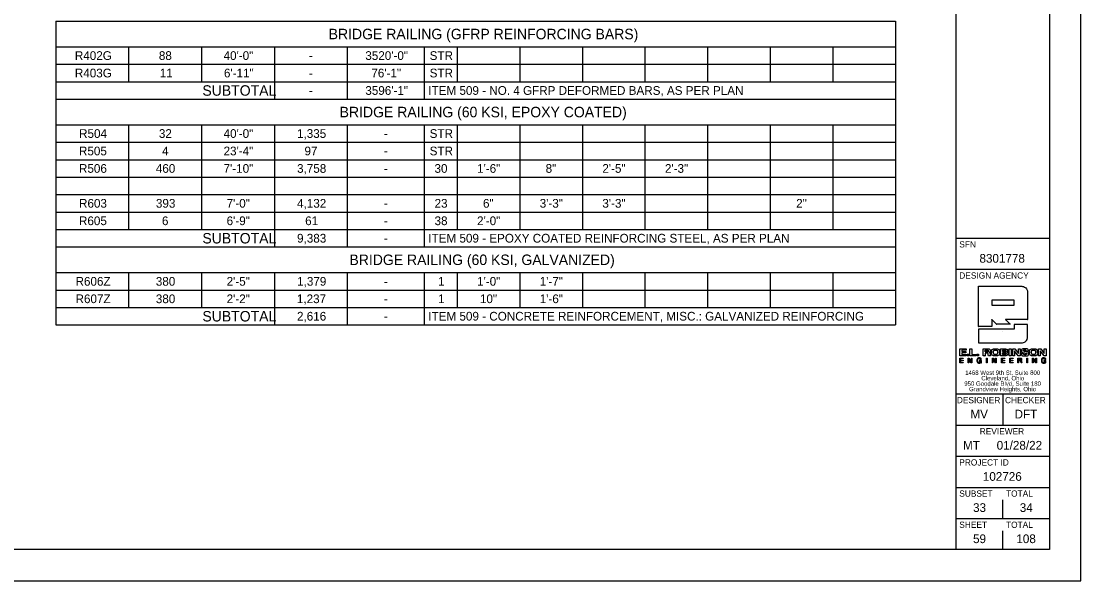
# Model space of a CAD drawing. Extents: x 0 to 34, y 0 to 22.
# Drawn here: x 17 to 34, y 0 to 8.98 of the extents above; entities that cross this region are included whole.
import ezdxf

# ---------------------------------------------------------------- set-up
doc = ezdxf.new("R2010")
doc.units = 0
for name, color, linetype in [('Default', 7, 'Continuous'), ('SH_Border', 7, 'Continuous'), ('SH_Cut_Line', 7, 'Continuous'), ('SH_Data', 7, 'Continuous')]:
    doc.layers.add(name, color=color, linetype=linetype)

msp = doc.modelspace()

# ---------------------------------------------------------------- linework, layer by layer
at = {"layer": 'Default'}
for p, q in [((17.554, 8.981), (31.027, 8.981)), ((17.554, 8.981), (17.554, 4.106)), ((31.027, 8.981), (31.027, 4.106)), ((17.554, 8.569), (31.027, 8.569)), ((18.723, 8.569), (18.723, 8.009)), ((19.892, 8.569), (19.892, 8.009)), ((21.062, 8.569), (21.062, 7.729)), ((22.231, 8.569), (22.231, 7.729)), ((23.467, 8.569), (23.467, 7.729)), ((23.994, 8.569), (23.994, 8.009)), ((24.998, 8.569), (24.998, 8.009)), ((26.003, 8.569), (26.003, 8.009)), ((27.008, 8.569), (27.008, 8.009)), ((28.013, 8.569), (28.013, 8.009)), ((29.017, 8.569), (29.017, 8.009)), ((30.022, 8.569), (30.022, 8.009)), ((17.554, 8.289), (31.027, 8.289)), ((17.554, 8.009), (31.027, 8.009)), ((17.554, 7.729), (31.027, 7.729)), ((17.554, 7.318), (31.027, 7.318)), ((18.723, 7.318), (18.723, 5.638)), ((19.892, 7.318), (19.892, 5.638)), ((21.062, 7.318), (21.062, 5.358)), ((22.231, 7.318), (22.231, 5.358)), ((23.467, 7.318), (23.467, 5.358)), ((23.994, 7.318), (23.994, 5.638)), ((24.998, 7.318), (24.998, 5.638)), ((26.003, 7.318), (26.003, 5.638)), ((27.008, 7.318), (27.008, 5.638)), ((28.013, 7.318), (28.013, 5.638)), ((29.017, 7.318), (29.017, 5.638)), ((30.022, 7.318), (30.022, 5.638)), ((17.554, 7.038), (31.027, 7.038)), ((17.554, 6.758), (31.027, 6.758)), ((17.554, 6.478), (31.027, 6.478)), ((17.554, 6.198), (31.027, 6.198)), ((17.554, 5.918), (31.027, 5.918)), ((17.554, 5.638), (31.027, 5.638)), ((17.554, 5.358), (31.027, 5.358)), ((17.554, 4.946), (31.027, 4.946)), ((18.723, 4.946), (18.723, 4.386)), ((19.892, 4.946), (19.892, 4.386)), ((21.062, 4.946), (21.062, 4.106)), ((22.231, 4.946), (22.231, 4.106)), ((23.467, 4.946), (23.467, 4.106)), ((23.994, 4.946), (23.994, 4.386)), ((24.998, 4.946), (24.998, 4.386)), ((26.003, 4.946), (26.003, 4.386)), ((27.008, 4.946), (27.008, 4.386)), ((28.013, 4.946), (28.013, 4.386)), ((29.017, 4.946), (29.017, 4.386)), ((30.022, 4.946), (30.022, 4.386)), ((17.554, 4.666), (31.027, 4.666)), ((17.554, 4.386), (31.027, 4.386)), ((17.554, 4.106), (31.027, 4.106))]:
    msp.add_line(p, q, dxfattribs=at)
at = {"layer": 'SH_Border'}
for p, q in [((32, 0.5), (32, 21.5)), ((32, 5.5), (33.5, 5.5)), ((32, 5), (33.5, 5)), ((32, 3), (33.5, 3)), ((32.75, 3), (32.75, 2.5)), ((32, 2.5), (33.5, 2.5)), ((32, 2), (33.5, 2)), ((32, 1.5), (33.5, 1.5)), ((32, 1), (33.5, 1))]:
    msp.add_line(p, q, dxfattribs=at)
msp.add_lwpolyline([(1.5, 21.5), (33.5, 21.5), (33.5, 0.5), (1.5, 0.5)], close=True, dxfattribs=at)
at = {"layer": 'SH_Cut_Line'}
msp.add_lwpolyline([(0, 0), (34, 0), (34, 22), (0, 22)], close=True, dxfattribs=at)
at = {"layer": 'SH_Data'}
for p, q in [((32.929, 4.503), (32.574, 4.503)), ((32.574, 4.503), (32.574, 4.425)), ((32.574, 4.425), (32.929, 4.425)), ((32.929, 4.425), (32.929, 4.503)), ((32.75, 4), (32.75, 4)), ((32.463, 3.701), (32.463, 3.673)), ((32.743, 3.702), (32.743, 3.678)), ((32.743, 3.659), (32.743, 3.633)), ((33.001, 3.566), (33.001, 3.539)), ((33.001, 3.539), (33.023, 3.539)), ((32.75, 1), (32.75, 1.3)), ((32.75, 0.5), (32.75, 0.8)), ((32.375, 0.675), (32.375, 0.675))]:
    msp.add_line(p, q, dxfattribs=at)
for points in [[(32.059, 3.575), (32.114, 3.575), (32.114, 3.566), (32.07, 3.566), (32.07, 3.541), (32.111, 3.541), (32.111, 3.532), (32.07, 3.532), (32.07, 3.505), (32.114, 3.505), (32.114, 3.496), (32.059, 3.496), (32.059, 3.575)], [(32.06, 3.721), (32.161, 3.721), (32.161, 3.701), (32.089, 3.701), (32.089, 3.678), (32.158, 3.678), (32.158, 3.658), (32.089, 3.658), (32.089, 3.633), (32.162, 3.633), (32.162, 3.613), (32.06, 3.613), (32.06, 3.721)], [(32.175, 3.639), (32.205, 3.639), (32.205, 3.613), (32.175, 3.613), (32.175, 3.639)], [(32.191, 3.575), (32.203, 3.575), (32.244, 3.511), (32.244, 3.511), (32.244, 3.575), (32.254, 3.575), (32.254, 3.496), (32.243, 3.496), (32.202, 3.559), (32.201, 3.559), (32.201, 3.496), (32.191, 3.496), (32.191, 3.575)], [(32.22, 3.721), (32.249, 3.721), (32.249, 3.634), (32.316, 3.634), (32.316, 3.613), (32.22, 3.613), (32.22, 3.721)], [(32.331, 3.639), (32.361, 3.639), (32.361, 3.613), (32.331, 3.613), (32.331, 3.639)], [(32.487, 3.575), (32.498, 3.575), (32.498, 3.496), (32.487, 3.496), (32.487, 3.575)], [(32.581, 3.575), (32.592, 3.575), (32.633, 3.511), (32.633, 3.511), (32.633, 3.575), (32.643, 3.575), (32.643, 3.496), (32.632, 3.496), (32.591, 3.559), (32.591, 3.559), (32.591, 3.496), (32.581, 3.496), (32.581, 3.575)], [(32.726, 3.575), (32.781, 3.575), (32.781, 3.566), (32.737, 3.566), (32.737, 3.541), (32.778, 3.541), (32.778, 3.532), (32.737, 3.532), (32.737, 3.505), (32.781, 3.505), (32.781, 3.496), (32.726, 3.496), (32.726, 3.575)], [(32.851, 3.721), (32.881, 3.721), (32.881, 3.613), (32.851, 3.613), (32.851, 3.721)], [(32.859, 3.575), (32.913, 3.575), (32.913, 3.566), (32.869, 3.566), (32.869, 3.541), (32.91, 3.541), (32.91, 3.532), (32.869, 3.532), (32.869, 3.505), (32.913, 3.505), (32.913, 3.496), (32.859, 3.496), (32.859, 3.575)], [(32.999, 3.721), (33.027, 3.721), (33.027, 3.613), (32.995, 3.613), (32.936, 3.689), (32.936, 3.689), (32.936, 3.613), (32.907, 3.613), (32.907, 3.721), (32.941, 3.721), (32.999, 3.646), (32.999, 3.646), (32.999, 3.721)], [(33.133, 3.575), (33.143, 3.575), (33.143, 3.496), (33.133, 3.496), (33.133, 3.575)], [(33.226, 3.575), (33.237, 3.575), (33.279, 3.511), (33.279, 3.511), (33.279, 3.575), (33.289, 3.575), (33.289, 3.496), (33.277, 3.496), (33.236, 3.559), (33.236, 3.559), (33.236, 3.496), (33.226, 3.496), (33.226, 3.575)], [(33.413, 3.721), (33.442, 3.721), (33.442, 3.613), (33.41, 3.613), (33.35, 3.689), (33.35, 3.689), (33.35, 3.613), (33.321, 3.613), (33.321, 3.721), (33.356, 3.721), (33.413, 3.646), (33.413, 3.646), (33.413, 3.721)]]:
    msp.add_lwpolyline(points, dxfattribs=at)
for points, degree in [([(32.356, 4.083), (32.356, 4.086), (32.356, 4.724), (32.356, 4.727)], 2), ([(32.356, 4.727), (32.36, 4.727), (33.03, 4.727), (33.034, 4.727), (33.096, 4.727), (33.147, 4.677), (33.147, 4.614)], 3), ([(33.147, 4.614), (33.147, 4.612), (33.147, 4.194), (33.147, 4.192)], 2), ([(32.929, 4.115), (32.929, 4.115), (33.147, 4.115), (33.147, 4.115), (33.147, 4.115), (33.147, 3.933), (33.147, 3.933), (33.147, 3.87), (33.096, 3.82), (33.034, 3.82), (33.034, 3.82), (32.356, 3.82), (32.356, 3.82), (32.356, 3.82), (32.356, 4.037), (32.356, 4.037), (32.356, 4.037), (32.929, 4.037), (32.929, 4.037), (32.929, 4.037), (32.929, 4.115), (32.929, 4.115)], 3), ([(32.574, 4.083), (32.573, 4.083), (32.357, 4.083), (32.356, 4.083)], 2), ([(32.645, 4.121), (32.645, 4.121), (32.574, 4.191), (32.574, 4.192)], 2), ([(32.574, 4.192), (32.574, 4.191), (32.574, 4.083), (32.574, 4.083)], 2), ([(32.866, 4.121), (32.865, 4.121), (32.646, 4.121), (32.645, 4.121)], 2), ([(33.147, 4.192), (33.145, 4.192), (32.795, 4.192), (32.793, 4.192)], 2), ([(32.793, 4.192), (32.793, 4.191), (32.866, 4.121), (32.866, 4.121)], 2), ([(32.396, 3.506), (32.39, 3.498), (32.38, 3.494), (32.37, 3.494), (32.347, 3.494), (32.333, 3.514), (32.333, 3.534), (32.333, 3.557), (32.346, 3.577), (32.37, 3.577), (32.388, 3.577), (32.401, 3.569), (32.404, 3.551), (32.404, 3.551), (32.394, 3.551), (32.394, 3.551), (32.392, 3.562), (32.382, 3.568), (32.37, 3.568), (32.351, 3.568), (32.344, 3.551), (32.344, 3.534), (32.344, 3.518), (32.353, 3.503), (32.37, 3.503), (32.387, 3.503), (32.396, 3.515), (32.396, 3.529), (32.396, 3.529), (32.371, 3.529), (32.371, 3.529), (32.371, 3.529), (32.371, 3.538), (32.371, 3.538), (32.371, 3.538), (32.405, 3.538), (32.405, 3.538), (32.405, 3.538), (32.405, 3.496), (32.405, 3.496), (32.405, 3.496), (32.398, 3.496), (32.398, 3.496), (32.398, 3.496), (32.396, 3.506), (32.396, 3.506)], 3), ([(32.433, 3.613), (32.433, 3.613), (32.433, 3.721), (32.433, 3.721)], 2), ([(32.433, 3.721), (32.433, 3.721), (32.512, 3.721), (32.512, 3.721), (32.542, 3.721), (32.545, 3.703), (32.546, 3.692)], 3), ([(32.463, 3.613), (32.462, 3.613), (32.433, 3.613), (32.433, 3.613)], 2), ([(32.499, 3.653), (32.499, 3.653), (32.463, 3.653), (32.463, 3.653)], 2), ([(32.463, 3.673), (32.463, 3.673), (32.502, 3.673), (32.502, 3.673), (32.508, 3.673), (32.516, 3.677), (32.516, 3.687), (32.516, 3.698), (32.507, 3.701), (32.5, 3.701), (32.5, 3.701), (32.463, 3.701), (32.463, 3.701), (32.463, 3.701), (32.463, 3.673), (32.463, 3.673)], 3), ([(32.463, 3.673), (32.476, 3.673), (32.489, 3.673), (32.508, 3.673), (32.516, 3.677), (32.516, 3.698), (32.507, 3.701), (32.488, 3.701), (32.475, 3.701), (32.463, 3.701)], 3), ([(32.463, 3.653), (32.463, 3.652), (32.463, 3.613), (32.463, 3.613)], 2), ([(32.518, 3.613), (32.516, 3.618), (32.516, 3.622), (32.516, 3.634), (32.515, 3.649), (32.508, 3.65), (32.499, 3.653)], 3), ([(32.55, 3.613), (32.55, 3.613), (32.518, 3.613), (32.518, 3.613)], 2), ([(32.546, 3.692), (32.544, 3.679), (32.542, 3.67), (32.53, 3.666)], 2), ([(32.53, 3.666), (32.53, 3.666), (32.53, 3.665), (32.53, 3.665)], 2), ([(32.53, 3.665), (32.543, 3.663), (32.544, 3.647), (32.544, 3.636)], 2), ([(32.544, 3.636), (32.544, 3.631), (32.548, 3.619), (32.55, 3.613)], 2), ([(32.631, 3.61), (32.573, 3.61), (32.567, 3.645), (32.565, 3.667), (32.564, 3.69), (32.573, 3.724), (32.631, 3.724)], 3), ([(32.631, 3.63), (32.658, 3.63), (32.667, 3.65), (32.667, 3.667), (32.667, 3.684), (32.658, 3.704), (32.631, 3.704), (32.604, 3.704), (32.595, 3.684), (32.595, 3.667), (32.595, 3.65), (32.604, 3.63), (32.631, 3.63)], 3), ([(32.631, 3.704), (32.604, 3.704), (32.595, 3.684), (32.595, 3.667), (32.595, 3.65), (32.604, 3.63), (32.631, 3.63)], 3), ([(32.631, 3.724), (32.69, 3.724), (32.695, 3.689), (32.697, 3.667), (32.699, 3.644), (32.69, 3.61), (32.631, 3.61)], 3), ([(32.631, 3.63), (32.658, 3.63), (32.667, 3.65), (32.667, 3.667), (32.667, 3.684), (32.658, 3.704), (32.631, 3.704)], 3), ([(32.714, 3.613), (32.714, 3.613), (32.714, 3.721), (32.714, 3.721)], 2), ([(32.714, 3.721), (32.714, 3.721), (32.795, 3.721), (32.795, 3.721)], 2), ([(32.829, 3.645), (32.827, 3.632), (32.824, 3.613), (32.791, 3.613), (32.791, 3.613), (32.714, 3.613), (32.714, 3.613)], 3), ([(32.743, 3.678), (32.743, 3.678), (32.784, 3.678), (32.784, 3.678), (32.791, 3.678), (32.796, 3.682), (32.796, 3.69), (32.796, 3.697), (32.793, 3.702), (32.78, 3.702), (32.78, 3.702), (32.743, 3.702), (32.743, 3.702), (32.743, 3.702), (32.743, 3.678), (32.743, 3.678)], 3), ([(32.743, 3.678), (32.757, 3.678), (32.771, 3.678), (32.791, 3.681), (32.791, 3.683), (32.792, 3.697), (32.793, 3.702), (32.768, 3.702), (32.756, 3.702), (32.743, 3.702)], 3), ([(32.743, 3.633), (32.743, 3.633), (32.787, 3.633), (32.787, 3.633), (32.796, 3.633), (32.8, 3.639), (32.8, 3.646), (32.8, 3.655), (32.794, 3.659), (32.784, 3.659), (32.784, 3.659), (32.743, 3.659), (32.743, 3.659), (32.743, 3.659), (32.743, 3.633), (32.743, 3.633)], 3), ([(32.743, 3.633), (32.758, 3.633), (32.772, 3.633), (32.796, 3.633), (32.8, 3.639), (32.8, 3.655), (32.794, 3.659), (32.77, 3.659), (32.757, 3.659), (32.743, 3.659)], 3), ([(32.795, 3.721), (32.81, 3.718), (32.826, 3.714), (32.826, 3.694)], 2), ([(32.826, 3.694), (32.824, 3.686), (32.822, 3.675), (32.812, 3.672)], 2), ([(32.812, 3.672), (32.812, 3.672), (32.812, 3.672), (32.812, 3.672)], 2), ([(32.812, 3.672), (32.824, 3.67), (32.827, 3.656), (32.829, 3.645)], 2), ([(32.991, 3.575), (32.991, 3.575), (33.027, 3.575), (33.028, 3.575), (33.042, 3.575), (33.051, 3.567), (33.051, 3.554)], 3), ([(32.991, 3.496), (32.991, 3.497), (32.991, 3.574), (32.991, 3.575)], 2), ([(33.126, 3.69), (33.124, 3.704), (33.111, 3.706), (33.099, 3.706), (33.087, 3.706), (33.079, 3.7), (33.079, 3.693), (33.079, 3.687), (33.084, 3.684), (33.091, 3.683), (33.091, 3.683), (33.128, 3.677), (33.128, 3.677), (33.148, 3.673), (33.163, 3.666), (33.163, 3.646), (33.163, 3.626), (33.149, 3.61), (33.107, 3.61), (33.08, 3.61), (33.046, 3.613), (33.045, 3.647), (33.045, 3.647), (33.079, 3.647), (33.079, 3.647), (33.079, 3.632), (33.094, 3.629), (33.107, 3.629), (33.121, 3.629), (33.13, 3.634), (33.13, 3.643), (33.13, 3.651), (33.123, 3.654), (33.112, 3.655), (33.112, 3.655), (33.085, 3.66), (33.085, 3.66), (33.066, 3.662), (33.047, 3.668), (33.047, 3.69), (33.047, 3.715), (33.067, 3.724), (33.101, 3.724), (33.124, 3.724), (33.157, 3.721), (33.159, 3.69), (33.159, 3.69), (33.126, 3.69), (33.126, 3.69)], 3), ([(33.242, 3.61), (33.183, 3.61), (33.178, 3.645), (33.176, 3.667), (33.174, 3.69), (33.183, 3.724), (33.242, 3.724)], 3), ([(33.242, 3.63), (33.269, 3.63), (33.278, 3.65), (33.278, 3.667), (33.278, 3.684), (33.269, 3.704), (33.242, 3.704), (33.215, 3.704), (33.205, 3.684), (33.205, 3.667), (33.205, 3.65), (33.215, 3.63), (33.242, 3.63)], 3), ([(33.242, 3.704), (33.215, 3.704), (33.205, 3.684), (33.205, 3.667), (33.205, 3.65), (33.215, 3.63), (33.242, 3.63)], 3), ([(33.242, 3.724), (33.3, 3.724), (33.306, 3.689), (33.308, 3.667), (33.309, 3.644), (33.3, 3.61), (33.242, 3.61)], 3), ([(33.242, 3.63), (33.269, 3.63), (33.278, 3.65), (33.278, 3.667), (33.278, 3.684), (33.269, 3.704), (33.242, 3.704)], 3), ([(33.43, 3.506), (33.424, 3.498), (33.414, 3.494), (33.405, 3.494), (33.382, 3.494), (33.368, 3.514), (33.368, 3.534), (33.368, 3.557), (33.38, 3.577), (33.405, 3.577), (33.422, 3.577), (33.436, 3.569), (33.439, 3.551), (33.439, 3.551), (33.429, 3.551), (33.429, 3.551), (33.426, 3.562), (33.417, 3.568), (33.405, 3.568), (33.386, 3.568), (33.378, 3.551), (33.378, 3.534), (33.378, 3.518), (33.388, 3.503), (33.405, 3.503), (33.421, 3.503), (33.431, 3.515), (33.43, 3.529), (33.43, 3.529), (33.405, 3.529), (33.405, 3.529), (33.405, 3.529), (33.405, 3.538), (33.405, 3.538), (33.405, 3.538), (33.44, 3.538), (33.44, 3.538), (33.44, 3.538), (33.44, 3.496), (33.44, 3.496), (33.44, 3.496), (33.433, 3.496), (33.433, 3.496), (33.433, 3.496), (33.43, 3.506), (33.43, 3.506)], 3), ([(33.001, 3.496), (33.001, 3.496), (32.991, 3.496), (32.991, 3.496)], 2), ([(33.023, 3.539), (33.033, 3.539), (33.041, 3.541), (33.041, 3.552), (33.041, 3.56), (33.037, 3.566), (33.027, 3.566), (33.027, 3.566), (33.001, 3.566), (33.001, 3.566), (33.001, 3.566), (33.001, 3.539), (33.001, 3.539), (33.001, 3.539), (33.023, 3.539), (33.023, 3.539)], 3), ([(33.023, 3.539), (33.033, 3.539), (33.041, 3.541), (33.041, 3.56), (33.037, 3.566), (33.018, 3.566), (33.01, 3.566), (33.001, 3.566)], 3), ([(33.04, 3.516), (33.038, 3.523), (33.037, 3.53), (33.027, 3.53), (33.027, 3.53), (33.001, 3.53), (33.001, 3.53)], 3), ([(33.001, 3.53), (33.001, 3.53), (33.001, 3.496), (33.001, 3.496)], 2), ([(33.051, 3.554), (33.049, 3.545), (33.047, 3.537), (33.038, 3.534)], 2), ([(33.038, 3.534), (33.038, 3.534), (33.038, 3.534), (33.038, 3.534)], 2), ([(33.038, 3.534), (33.044, 3.529), (33.047, 3.525), (33.048, 3.518)], 2), ([(33.043, 3.496), (33.042, 3.5), (33.041, 3.508), (33.04, 3.516)], 2), ([(33.054, 3.496), (33.054, 3.496), (33.043, 3.496), (33.043, 3.496)], 2), ([(33.048, 3.518), (33.049, 3.51), (33.052, 3.502), (33.054, 3.496)], 2)]:
    msp.add_open_spline(points, degree=degree, dxfattribs=at)

# ---------------------------------------------------------------- texts
at = {"layer": 'Default'}
for s, height, p in [('BRIDGE RAILING (GFRP REINFORCING BARS)', 0.168, (21.933, 8.691)), ('R402G', 0.14, (17.861, 8.359)), ('88', 0.14, (19.209, 8.359)), ('40\'-0"', 0.14, (20.247, 8.359)), ('3520\'-0"', 0.14, (22.521, 8.359)), ('STR', 0.14, (23.553, 8.359)), ('-', 0.14, (21.617, 8.359)), ('R403G', 0.14, (17.861, 8.079)), ('11', 0.14, (19.223, 8.079)), ('6\'-11"', 0.14, (20.253, 8.079)), ('76\'-1"', 0.14, (22.618, 8.079)), ('STR', 0.14, (23.553, 8.079)), ('-', 0.14, (21.617, 8.079)), ('SUBTOTAL', 0.168, (19.907, 7.785)), ('-', 0.154, (21.614, 7.795)), ('3596\'-1"', 0.14, (22.521, 7.799)), ('ITEM 509 - NO. 4 GFRP DEFORMED BARS, AS PER PLAN', 0.14, (23.532, 7.799)), ('BRIDGE RAILING (60 KSI, EPOXY COATED)', 0.168, (22.109, 7.439)), ('R504', 0.14, (17.929, 7.108)), ('32', 0.14, (19.209, 7.108)), ('40\'-0"', 0.14, (20.247, 7.108)), ('1,335', 0.14, (21.425, 7.108)), ('-', 0.14, (22.82, 7.108)), ('STR', 0.14, (23.553, 7.108)), ('R505', 0.14, (17.927, 6.828)), ('4', 0.14, (19.26, 6.828)), ('23\'-4"', 0.14, (20.247, 6.828)), ('97', 0.14, (21.545, 6.828)), ('-', 0.14, (22.82, 6.828)), ('STR', 0.14, (23.553, 6.828)), ('R506', 0.14, (17.927, 6.548)), ('460', 0.14, (19.16, 6.548)), ('7\'-10"', 0.14, (20.247, 6.548)), ('3,758', 0.14, (21.426, 6.548)), ('30', 0.14, (23.631, 6.548)), ('1\'-6"', 0.14, (24.314, 6.548)), ('8"', 0.14, (25.414, 6.548)), ('2\'-5"', 0.14, (26.324, 6.548)), ('2\'-3"', 0.14, (27.328, 6.548)), ('-', 0.14, (22.82, 6.548)), ('R603', 0.14, (17.928, 5.988)), ('393', 0.14, (19.161, 5.988)), ('7\'-0"', 0.14, (20.296, 5.988)), ('4,132', 0.14, (21.426, 5.988)), ('23', 0.14, (23.632, 5.988)), ('6"', 0.14, (24.409, 5.988)), ('3\'-3"', 0.14, (25.319, 5.988)), ('3\'-3"', 0.14, (26.324, 5.988)), ('2"', 0.14, (29.433, 5.988)), ('-', 0.14, (22.82, 5.988)), ('R605', 0.14, (17.927, 5.708)), ('6', 0.14, (19.258, 5.708)), ('6\'-9"', 0.14, (20.296, 5.708)), ('61', 0.14, (21.556, 5.708)), ('38', 0.14, (23.632, 5.708)), ('2\'-0"', 0.14, (24.314, 5.708)), ('-', 0.14, (22.82, 5.708)), ('SUBTOTAL', 0.168, (19.907, 5.414)), ('9,383', 0.14, (21.426, 5.428)), ('-', 0.14, (22.82, 5.428)), ('ITEM 509 - EPOXY COATED REINFORCING STEEL, AS PER PLAN', 0.14, (23.532, 5.428)), ('BRIDGE RAILING (60 KSI, GALVANIZED)', 0.168, (22.266, 5.068)), ('R606Z', 0.14, (17.872, 4.736)), ('380', 0.14, (19.16, 4.736)), ('2\'-5"', 0.14, (20.296, 4.736)), ('1,379', 0.14, (21.427, 4.736)), ('-', 0.14, (22.82, 4.736)), ('1', 0.14, (23.688, 4.736)), ('1\'-0"', 0.14, (24.314, 4.736)), ('1\'-7"', 0.14, (25.319, 4.736)), ('R607Z', 0.14, (17.872, 4.456)), ('380', 0.14, (19.16, 4.456)), ('2\'-2"', 0.14, (20.296, 4.456)), ('1,237', 0.14, (21.423, 4.456)), ('1', 0.14, (23.688, 4.456)), ('10"', 0.14, (24.36, 4.456)), ('1\'-6"', 0.14, (25.319, 4.456)), ('-', 0.14, (22.82, 4.456)), ('SUBTOTAL', 0.168, (19.907, 4.162)), ('2,616', 0.14, (21.425, 4.176)), ('ITEM 509 - CONCRETE REINFORCEMENT, MISC.: GALVANIZED REINFORCING', 0.14, (23.532, 4.176)), ('-', 0.14, (22.82, 4.176))]:
    msp.add_text(s, height=height, dxfattribs=at).set_placement(p)
at = {"layer": 'SH_Data'}
for s, height, p in [('SFN', 0.1, (32.05, 5.35)), ('8301778', 0.14, (32.374, 5.105)), ('DESIGN AGENCY', 0.1, (32.05, 4.85)), ('1468 West 9th St, Suite 800', 0.07, (32.145, 3.305)), ('Cleveland, Ohio', 0.07, (32.404, 3.217)), ('950 Goodale Blvd, Suite 180', 0.07, (32.13, 3.13)), ('Grandview Heights, Ohio', 0.07, (32.208, 3.042)), ('DESIGNER', 0.1, (32.011, 2.85)), ('CHECKER', 0.1, (32.784, 2.85)), ('MV', 0.14, (32.229, 2.605)), ('DFT', 0.14, (32.937, 2.605)), ('REVIEWER', 0.1, (32.378, 2.35)), ('MT', 0.14, (32.111, 2.105)), ('01/28/22', 0.14, (32.65, 2.105)), ('PROJECT ID', 0.1, (32.05, 1.85)), ('102726', 0.14, (32.428, 1.605)), ('SUBSET', 0.1, (32.05, 1.35)), ('TOTAL', 0.1, (32.8, 1.35)), ('33', 0.14, (32.271, 1.105)), ('34', 0.14, (33.021, 1.105)), ('SHEET', 0.1, (32.05, 0.85)), ('TOTAL', 0.1, (32.8, 0.85)), ('59', 0.14, (32.271, 0.605)), ('108', 0.14, (32.966, 0.605))]:
    msp.add_text(s, height=height, dxfattribs=at).set_placement(p)

doc.saveas('drawing.dxf')
